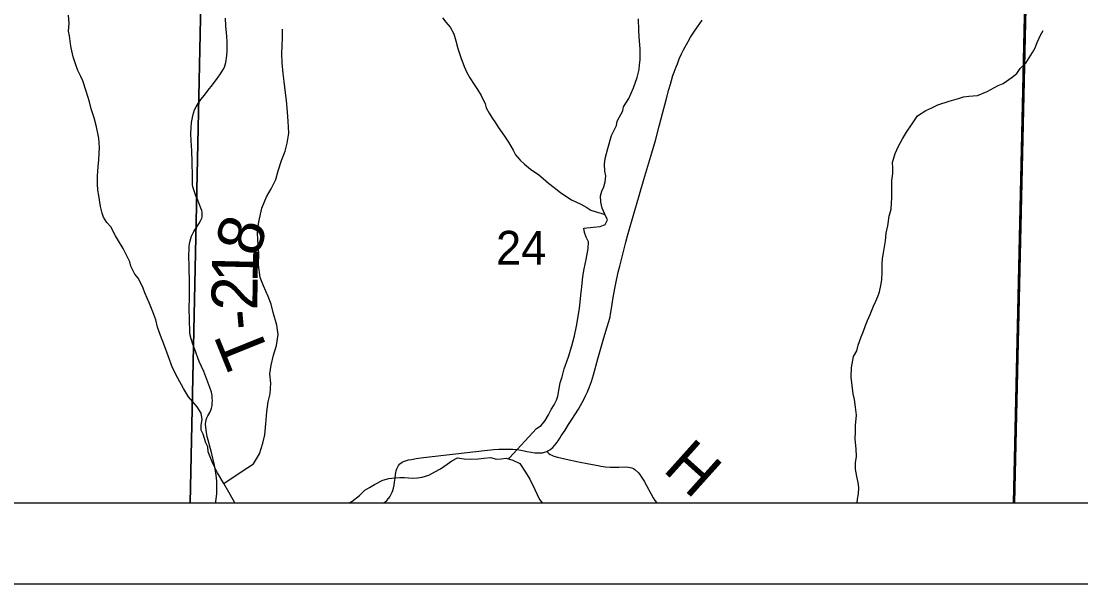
# Model space of a CAD drawing. Extents: x 0 to 34, y 0 to 22.
# Drawn here: x 5.283 to 6.594, y 14 to 14.696 of the extents above; entities that cross this region are included whole.
import ezdxf

# ---------------------------------------------------------------- set-up
doc = ezdxf.new("R2010")
doc.units = 0
for name, color, linetype in [('GM_X_Corporation', 7, 'Continuous'), ('GM_X_County_Road_Text', 7, 'Continuous'), ('GM_X_Interchange_Ramps', 7, 'Continuous'), ('GM_X_Interstate_Route', 7, 'Continuous'), ('GM_X_Section', 7, 'Continuous'), ('GM_X_Township_Road_Text', 7, 'Continuous'), ('GM_X_Unincorporated_Text', 7, 'Continuous'), ('SH_Cut_Line', 7, 'Continuous'), ('SH_Data', 7, 'Continuous')]:
    doc.layers.add(name, color=color, linetype=linetype)

msp = doc.modelspace()

# ---------------------------------------------------------------- linework, layer by layer
at = {"layer": 'GM_X_Corporation'}
msp.add_lwpolyline([(5.7316, 14.1), (5.733, 14.101), (5.7354, 14.1032), (5.7375, 14.1055), (5.7392, 14.1077), (5.741, 14.1107), (5.7423, 14.1135), (5.743, 14.1153), (5.7437, 14.1182), (5.7445, 14.1222), (5.7451, 14.1259), (5.7457, 14.1306), (5.7463, 14.1353), (5.7466, 14.1372), (5.7472, 14.1399), (5.7479, 14.1421), (5.7486, 14.1439), (5.7499, 14.1462), (5.7516, 14.1483), (5.7531, 14.1494), (5.7545, 14.1504), (5.756, 14.1511), (5.7588, 14.1522), (5.7625, 14.1532), (5.7662, 14.1539), (5.772, 14.1549), (5.781, 14.1561), (5.8063, 14.1593), (5.8564, 14.1649), (5.8678, 14.166), (5.8743, 14.1664), (5.8809, 14.1666), (5.8915, 14.1665), (5.8968, 14.166), (5.9015, 14.1653), (5.9057, 14.1645), (5.9089, 14.1637), (5.9141, 14.1628), (5.9187, 14.1622), (5.9224, 14.1619), (5.9281, 14.1622), (5.9309, 14.1629), (5.9335, 14.1638), (5.9358, 14.165), (5.9373, 14.1659), (5.9395, 14.1674), (5.9411, 14.1688), (5.9431, 14.171), (5.9452, 14.1736), (5.9475, 14.177), (5.9496, 14.1802), (5.9515, 14.183), (5.9561, 14.1901), (5.9606, 14.197), (5.9647, 14.2034), (5.9681, 14.2089), (5.9726, 14.2162), (5.9798, 14.2289), (5.9816, 14.2325), (5.984, 14.2376), (5.9865, 14.2436), (5.9888, 14.2503), (5.9914, 14.2586), (5.9967, 14.2782), (6.0043, 14.3041), (6.0083, 14.3179), (6.0103, 14.3246), (6.0118, 14.3304), (6.0125, 14.3334), (6.0141, 14.343), (6.0153, 14.3516), (6.0177, 14.3653), (6.0184, 14.3695), (6.022, 14.3855), (6.0238, 14.393), (6.0315, 14.4227), (6.0336, 14.4304), (6.0368, 14.4421), (6.0396, 14.4521), (6.0481, 14.4817), (6.0536, 14.5003), (6.0636, 14.5333), (6.0679, 14.5483), (6.0727, 14.5663), (6.0768, 14.5818), (6.0812, 14.5986), (6.0846, 14.6116), (6.0865, 14.6183), (6.0878, 14.6227), (6.0896, 14.6287), (6.0912, 14.6331), (6.0936, 14.6398), (6.0951, 14.6434), (6.0975, 14.6493), (6.1004, 14.6557), (6.1029, 14.6608), (6.1083, 14.6708), (6.1115, 14.6764), (6.1155, 14.6825), (6.1199, 14.689), (6.126, 14.6974)], dxfattribs=at)
at = {"layer": 'GM_X_Interchange_Ramps'}
msp.add_lwpolyline([(2.1, 17.9098), (2.1, 14.1), (6.5113, 14.1), (6.5389, 15.3228), (6.5411, 15.4243), (6.5572, 16.1864), (6.5647, 16.5359), (6.5883, 17.471), (6.5943, 17.9356)], dxfattribs=at)
msp.add_lwpolyline([(6.5113, 14.1), (8.9, 14.1), (8.9, 17.8921), (8.5492, 17.9006), (8.3297, 17.9059), (7.6027, 17.9156), (6.5943, 17.9356), (6.5883, 17.471), (6.5647, 16.5359), (6.5572, 16.1864), (6.5411, 15.4243), (6.5389, 15.3228)], close=True, dxfattribs=at)
at = {"layer": 'GM_X_Interstate_Route'}
for points in [[(5.5239, 14.1), (5.5241, 14.1013), (5.5245, 14.1051), (5.5247, 14.1078), (5.525, 14.1116), (5.5252, 14.1168), (5.525, 14.1271), (5.5248, 14.1306), (5.5244, 14.1345), (5.524, 14.1374), (5.5231, 14.1419), (5.5222, 14.1467), (5.5186, 14.1623), (5.5133, 14.1821), (5.5123, 14.1873), (5.5115, 14.1932), (5.5111, 14.1977), (5.5114, 14.2001), (5.5119, 14.2029), (5.513, 14.2055), (5.5141, 14.2077), (5.5164, 14.2117), (5.5176, 14.2146), (5.5187, 14.2174), (5.5192, 14.2205), (5.5196, 14.2233), (5.5198, 14.2266), (5.5196, 14.2293), (5.5192, 14.2328), (5.5184, 14.2371), (5.5165, 14.2428), (5.509, 14.2625), (5.5034, 14.2752), (5.4979, 14.2897), (5.4954, 14.2963), (5.4934, 14.3031), (5.4923, 14.3075), (5.4919, 14.3112), (5.4917, 14.3165), (5.4914, 14.3215), (5.4913, 14.3282), (5.4911, 14.339), (5.4913, 14.356), (5.4915, 14.3739), (5.4911, 14.3909), (5.4907, 14.4072), (5.4908, 14.413), (5.491, 14.4174), (5.4915, 14.4207), (5.4923, 14.4243), (5.494, 14.4301), (5.4968, 14.4357), (5.5001, 14.441), (5.503, 14.4453), (5.505, 14.449), (5.5067, 14.4524), (5.507, 14.4538), (5.5072, 14.4557), (5.5071, 14.4576), (5.5069, 14.4592), (5.5065, 14.4618), (5.5053, 14.4647), (5.504, 14.4682), (5.5027, 14.4712), (5.5015, 14.4745), (5.4992, 14.4799), (5.4975, 14.485), (5.4956, 14.4912), (5.4952, 14.4942), (5.4949, 14.4992), (5.495, 14.5039), (5.4948, 14.5219), (5.4944, 14.5357), (5.4939, 14.5423), (5.4934, 14.548), (5.4931, 14.557), (5.4933, 14.5641), (5.4938, 14.5708), (5.4949, 14.5768), (5.4964, 14.5823), (5.4977, 14.5864), (5.4996, 14.59), (5.5019, 14.5942), (5.5054, 14.5991), (5.5099, 14.6046), (5.5144, 14.6108), (5.5198, 14.6173), (5.5256, 14.6251), (5.527, 14.6269), (5.5298, 14.6311), (5.5329, 14.6361), (5.5345, 14.6393), (5.5355, 14.6422), (5.5363, 14.645), (5.5368, 14.6477), (5.5372, 14.6502), (5.5376, 14.6542), (5.538, 14.6587), (5.5381, 14.6642), (5.538, 14.6703), (5.5376, 14.6776), (5.5365, 14.6904), (5.5357, 14.6999)], [(5.9335, 14.1638), (5.9351, 14.1618), (5.936, 14.161), (5.9377, 14.1599), (5.9396, 14.159), (5.9423, 14.158), (5.9469, 14.1566), (5.9577, 14.1542), (5.9728, 14.151), (5.9856, 14.1484), (5.997, 14.1463), (6.0006, 14.1456), (6.0062, 14.1448), (6.0121, 14.1443), (6.0174, 14.1441), (6.0229, 14.1442), (6.0312, 14.1445), (6.0347, 14.1443), (6.0366, 14.144), (6.0389, 14.1435), (6.0407, 14.1426), (6.0427, 14.1413), (6.0465, 14.1375), (6.0485, 14.1352), (6.0508, 14.1318), (6.0539, 14.127), (6.0652, 14.1065), (6.0674, 14.103), (6.0699, 14.1)]]:
    msp.add_lwpolyline(points, dxfattribs=at)
at = {"layer": 'GM_X_Township_Road_Text'}
msp.add_line((6.5446, 14.6787), (6.5479, 14.6845), dxfattribs=at)
for points in [[(5.5474, 14.1), (5.5452, 14.1037), (5.5401, 14.1132), (5.5339, 14.1241), (5.5261, 14.1373), (5.5203, 14.1487), (5.5144, 14.1634), (5.5139, 14.1695), (5.5116, 14.1744), (5.5084, 14.185), (5.5057, 14.1899), (5.5059, 14.1964), (5.507, 14.2033), (5.5057, 14.2109), (5.5007, 14.2188), (5.4903, 14.2312), (5.4841, 14.2418), (5.4771, 14.2542), (5.4705, 14.2671), (5.4649, 14.2822), (5.4606, 14.2943), (5.4555, 14.3072), (5.4519, 14.3174), (5.4495, 14.3265), (5.446, 14.3363), (5.4417, 14.3469), (5.4362, 14.3598), (5.4338, 14.3659), (5.4283, 14.3776), (5.4237, 14.3832), (5.4186, 14.393), (5.4174, 14.3983), (5.4143, 14.4048), (5.4092, 14.415), (5.4034, 14.4244), (5.3999, 14.4304), (5.3941, 14.4418), (5.3891, 14.447), (5.3848, 14.4534), (5.3832, 14.4584), (5.3812, 14.4667), (5.3791, 14.4804), (5.3779, 14.4872), (5.3774, 14.4948), (5.3773, 14.5043), (5.3782, 14.5161), (5.3793, 14.5241), (5.3795, 14.5329), (5.3798, 14.5398), (5.3792, 14.5515), (5.3764, 14.5652), (5.3732, 14.5766), (5.3696, 14.5876), (5.3676, 14.5963), (5.3636, 14.6096), (5.3593, 14.6224), (5.3569, 14.6277), (5.353, 14.6349), (5.3503, 14.6432), (5.3475, 14.6519), (5.345, 14.6629), (5.3442, 14.6679), (5.3429, 14.6778), (5.3417, 14.6838), (5.3423, 14.6934), (5.3418, 14.7036)], [(5.8045, 14.7002), (5.8087, 14.695), (5.8141, 14.6886), (5.8184, 14.6806), (5.8208, 14.6719), (5.8236, 14.6621), (5.8272, 14.6511), (5.8311, 14.6401), (5.8346, 14.6325), (5.8381, 14.6261), (5.8436, 14.6178), (5.8478, 14.6114), (5.8525, 14.6043), (5.8572, 14.5937), (5.8587, 14.5888), (5.8622, 14.5823), (5.8654, 14.5767), (5.87, 14.5703), (5.8735, 14.565), (5.8785, 14.5578), (5.882, 14.5526), (5.8862, 14.5462), (5.8921, 14.5364), (5.8948, 14.5307), (5.9006, 14.5243), (5.906, 14.5191), (5.9132, 14.5131), (5.9236, 14.506), (5.9289, 14.5015), (5.9358, 14.4955), (5.9427, 14.4903), (5.9504, 14.4843), (5.9584, 14.4787), (5.9641, 14.475), (5.9756, 14.4695), (5.9832, 14.4654), (5.9882, 14.4624), (5.9946, 14.4603), (6.0004, 14.4584), (6.0055, 14.4569)], [(5.8867, 14.1544), (5.8873, 14.1558), (5.921, 14.192), (5.9266, 14.1958), (5.9314, 14.202), (5.9358, 14.2089), (5.9388, 14.2158), (5.9425, 14.2212), (5.9454, 14.227), (5.9472, 14.2323), (5.949, 14.2415), (5.95, 14.2487), (5.9526, 14.256), (5.9551, 14.2659), (5.9605, 14.2809), (5.9645, 14.2942), (5.9677, 14.3068), (5.9702, 14.3187), (5.9723, 14.3305), (5.9741, 14.3408), (5.9747, 14.3484), (5.9757, 14.3572), (5.9771, 14.3675), (5.978, 14.3801), (5.9798, 14.3896), (5.9823, 14.4011), (5.9847, 14.4148), (5.9853, 14.4232), (5.9822, 14.4289), (5.9803, 14.4345), (5.9794, 14.4399), (5.9908, 14.4412), (5.9995, 14.4421), (6.0059, 14.4444), (6.0088, 14.4502), (6.0053, 14.4574), (6.0022, 14.4649), (6.0005, 14.4721), (6, 14.4798), (6.0018, 14.4859), (6.004, 14.4912), (6.0058, 14.4973), (6.0065, 14.5046), (6.0053, 14.5103), (6.0051, 14.519), (6.0058, 14.5263), (6.009, 14.5385), (6.0137, 14.5546), (6.02, 14.5672), (6.0207, 14.5722), (6.0277, 14.5852), (6.0283, 14.5902), (6.035, 14.6006), (6.0409, 14.6136), (6.0452, 14.6262), (6.0477, 14.6361), (6.0484, 14.6419), (6.0491, 14.6483), (6.0489, 14.6617), (6.0479, 14.6761), (6.0474, 14.6849), (6.0472, 14.6989)], [(5.5339, 14.1241), (5.5567, 14.1392), (5.5704, 14.1483), (5.578, 14.1608), (5.5822, 14.1741), (5.5845, 14.1843), (5.586, 14.198), (5.5871, 14.2128), (5.5886, 14.225), (5.5913, 14.2348), (5.592, 14.2481), (5.5909, 14.2599), (5.5924, 14.2705), (5.5951, 14.2827), (5.5989, 14.2948), (5.6011, 14.3085), (5.5996, 14.3199), (5.595, 14.3355), (5.5923, 14.3461), (5.5889, 14.3556), (5.5828, 14.3685), (5.5786, 14.3788), (5.5766, 14.3947), (5.577, 14.4088), (5.5758, 14.4251), (5.5754, 14.435), (5.577, 14.4479), (5.5808, 14.4646), (5.5868, 14.4787), (5.5925, 14.4885), (5.5982, 14.5003), (5.6009, 14.5109), (5.6051, 14.5239), (5.6096, 14.5352), (5.6123, 14.5451), (5.6142, 14.5577), (5.6134, 14.5725), (5.6126, 14.5835), (5.6115, 14.5979), (5.6103, 14.6074), (5.6084, 14.6215), (5.6073, 14.6313), (5.6061, 14.6446), (5.6057, 14.656), (5.6061, 14.6655), (5.6064, 14.6754), (5.6064, 14.6864)], [(6.3177, 14.1), (6.3179, 14.1047), (6.3193, 14.1112), (6.3196, 14.1192), (6.3191, 14.1253), (6.3171, 14.1329), (6.3154, 14.1416), (6.3157, 14.1496), (6.3167, 14.1576), (6.3166, 14.1671), (6.3153, 14.1789), (6.3155, 14.1884), (6.3158, 14.1957), (6.3167, 14.2086), (6.3155, 14.2185), (6.3142, 14.228), (6.3126, 14.2348), (6.3113, 14.2455), (6.3104, 14.2557), (6.3106, 14.2675), (6.313, 14.2813), (6.3171, 14.2882), (6.3189, 14.2951), (6.3225, 14.3054), (6.3254, 14.3127), (6.328, 14.3196), (6.3305, 14.3257), (6.3338, 14.3333), (6.3379, 14.3433), (6.3408, 14.3498), (6.3434, 14.3556), (6.3452, 14.3613), (6.347, 14.3689), (6.348, 14.3762), (6.3486, 14.3861), (6.3485, 14.3956), (6.3491, 14.4025), (6.3502, 14.4093), (6.3516, 14.417), (6.3526, 14.4242), (6.3536, 14.4337), (6.3557, 14.4429), (6.3574, 14.4547), (6.3596, 14.4635), (6.3602, 14.4715), (6.3605, 14.4772), (6.3604, 14.4849), (6.3606, 14.4989), (6.3616, 14.5077), (6.3619, 14.5146), (6.3614, 14.5214), (6.3646, 14.5325), (6.3687, 14.5413), (6.3738, 14.5505), (6.3786, 14.5586), (6.3849, 14.5678), (6.3924, 14.579), (6.4025, 14.5856), (6.41, 14.5888), (6.4175, 14.5927), (6.4315, 14.5971), (6.4432, 14.6003), (6.4492, 14.6023), (6.456, 14.6032), (6.4666, 14.6041), (6.4786, 14.6092), (6.4921, 14.6167), (6.4982, 14.619), (6.5094, 14.6268), (6.5154, 14.6315), (6.5195, 14.6376), (6.5262, 14.6442), (6.5306, 14.6507), (6.5347, 14.6573), (6.538, 14.663), (6.5406, 14.6699), (6.5446, 14.6787)], [(5.6891, 14.1), (5.6921, 14.1017), (5.7018, 14.1091), (5.7085, 14.1157), (5.7142, 14.1192), (5.7202, 14.1227), (5.7307, 14.1282), (5.7382, 14.1302), (5.7454, 14.1311), (5.7515, 14.1316), (5.7575, 14.1313), (5.7674, 14.1307), (5.7734, 14.1311), (5.7795, 14.132), (5.7874, 14.1344), (5.7949, 14.1383), (5.802, 14.1422), (5.8103, 14.148), (5.8159, 14.1523), (5.823, 14.1558), (5.8314, 14.1545), (5.839, 14.1542), (5.8488, 14.1547), (5.856, 14.1556), (5.8639, 14.1561), (5.8711, 14.1543), (5.8772, 14.1544), (5.8832, 14.1552), (5.8916, 14.1531), (5.9, 14.1486), (5.907, 14.1381), (5.9124, 14.1294), (5.9186, 14.1166), (5.9245, 14.1041), (5.928, 14.1)]]:
    msp.add_lwpolyline(points, dxfattribs=at)
at = {"layer": 'GM_X_Unincorporated_Text'}
for points in [[(4.484, 14.1), (5.492, 14.1), (5.5097, 14.9125), (4.5059, 14.9222)], [(5.492, 14.1), (6.5122, 14.1), (6.5307, 14.8925), (5.5097, 14.9125)], [(6.5122, 14.1), (7.5285, 14.1), (7.5466, 14.8803), (6.5307, 14.8925)]]:
    msp.add_lwpolyline(points, close=True, dxfattribs=at)
at = {"layer": 'SH_Cut_Line'}
msp.add_lwpolyline([(2.1, 17.9098), (2.1, 14.1), (8.9, 14.1), (8.9, 17.8921), (8.5492, 17.9006), (8.3297, 17.9059), (7.6027, 17.9156), (6.5943, 17.9356), (6.24, 17.9427), (6.0729, 17.9463), (5.6339, 17.9555), (5.3871, 17.9608), (4.994, 17.969), (4.9368, 17.9702), (4.9267, 17.9702), (4.5919, 17.9719), (4.4481, 17.9728), (4.1825, 17.9744), (3.7128, 17.9822), (3.7063, 17.8588), (3.604, 17.8577), (2.9484, 17.8857), (2.6711, 17.8975), (2.4376, 17.9025)], close=True, dxfattribs=at)
at = {"layer": 'SH_Data'}
for p, q in [((2.1, 14.1), (8.9, 14.1)), ((2, 14), (9, 14))]:
    msp.add_line(p, q, dxfattribs=at)

# ---------------------------------------------------------------- texts
at = {"layer": 'GM_X_County_Road_Text'}
msp.add_text('24', height=0.04186, rotation=0, dxfattribs=at).set_placement((5.8707, 14.3948))
at = {"layer": 'GM_X_Section'}
for s, rotation, p in [('8', 71.9225, (5.5756, 14.4028)), ('1', 88.678, (5.5755, 14.3724)), ('2', 89.7378, (5.5754, 14.338)), ('-', 95.1211, (5.5774, 14.3163)), ('T', 111.9909, (5.5922, 14.2813)), ('H', 318.1002, (6.0757, 14.1402))]:
    msp.add_text(s, height=0.0568, rotation=rotation, dxfattribs=at).set_placement(p)

doc.saveas('drawing.dxf')
